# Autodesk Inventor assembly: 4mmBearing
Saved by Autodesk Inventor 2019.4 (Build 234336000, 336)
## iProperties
Created: 2020-04
Part Number: 4mmBearing
Document SubType Name: Assembly
Designer: Administrator
Title: 4mmBearing v4
Author: Administrator
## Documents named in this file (2)
- c:\worker\convert-fusion-r03\tmp\job-1\48\output\files\ccae6ef3-9f0e-42ff-b199-3a2c6474057a\4mmBearing v4.iam
- c:\worker\convert-fusion-r03\tmp\job-1\48\output\files\ccae6ef3-9f0e-42ff-b199-3a2c6474057a\4mmBearing.ipt
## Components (1 placed, 1 different names)
1. 4mmBearing:1
